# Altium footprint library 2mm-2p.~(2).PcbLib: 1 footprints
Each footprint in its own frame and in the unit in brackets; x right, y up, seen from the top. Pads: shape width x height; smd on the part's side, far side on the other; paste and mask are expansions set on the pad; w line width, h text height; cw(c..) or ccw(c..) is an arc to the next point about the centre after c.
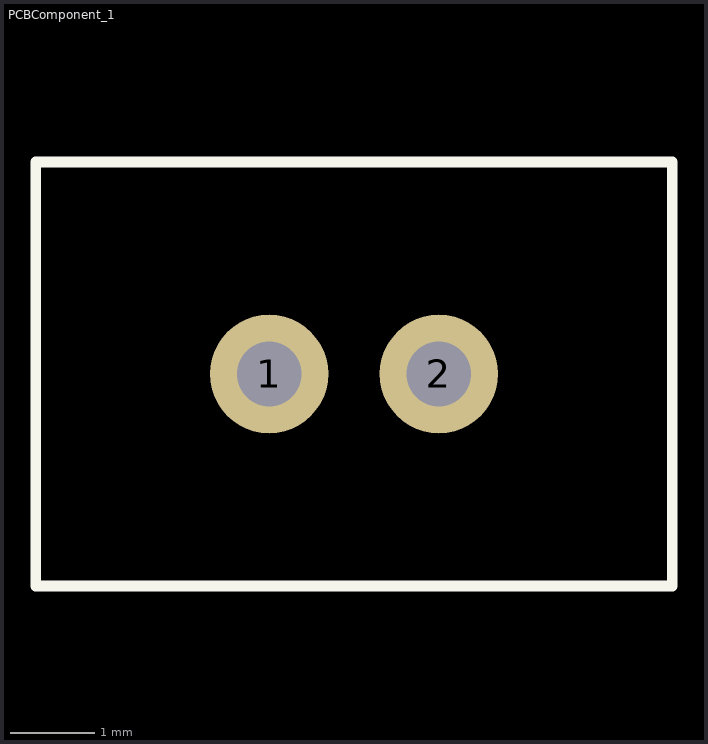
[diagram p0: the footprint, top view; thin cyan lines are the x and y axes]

## PCBComponent_1 [mil]
pads (2):
  round 55 hole 30: 1(-49803.15,-49606.3) 2(-49724.41,-49606.3)
Top Overlay:
  lines w5: -49911.42,-49704.72 -49911.42,-49507.87 -49616.14,-49507.87 -49616.14,-49704.72 -49911.42,-49704.72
